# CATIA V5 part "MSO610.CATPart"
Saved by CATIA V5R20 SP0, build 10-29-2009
Part number: MSO610
Definition: NONE
Nomenclature: MSO610
Source: Unknown
Description: MSO610
Bounding box of the stored display mesh (mm): x 0 to 12, y -5 to 5, z -5 to 5
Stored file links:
  C:\Users\Utente\Desktop\IO LAVORO\3D X SITO CF\X SITO\PLASTICA\CFMR\MSO610.CATPart
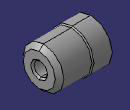
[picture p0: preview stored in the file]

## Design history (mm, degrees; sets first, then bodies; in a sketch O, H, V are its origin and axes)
Body1 "MSO610" (main body)
  Solid1: solid without history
